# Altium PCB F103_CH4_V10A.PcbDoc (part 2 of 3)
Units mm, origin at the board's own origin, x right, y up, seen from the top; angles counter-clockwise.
Board outline 100.1 x 70.1 mm, 2 copper layers (TOP, BOTTOM), stack 1.6 mm thick; 116 components, 94 nets, 464 pads, 459 vias.
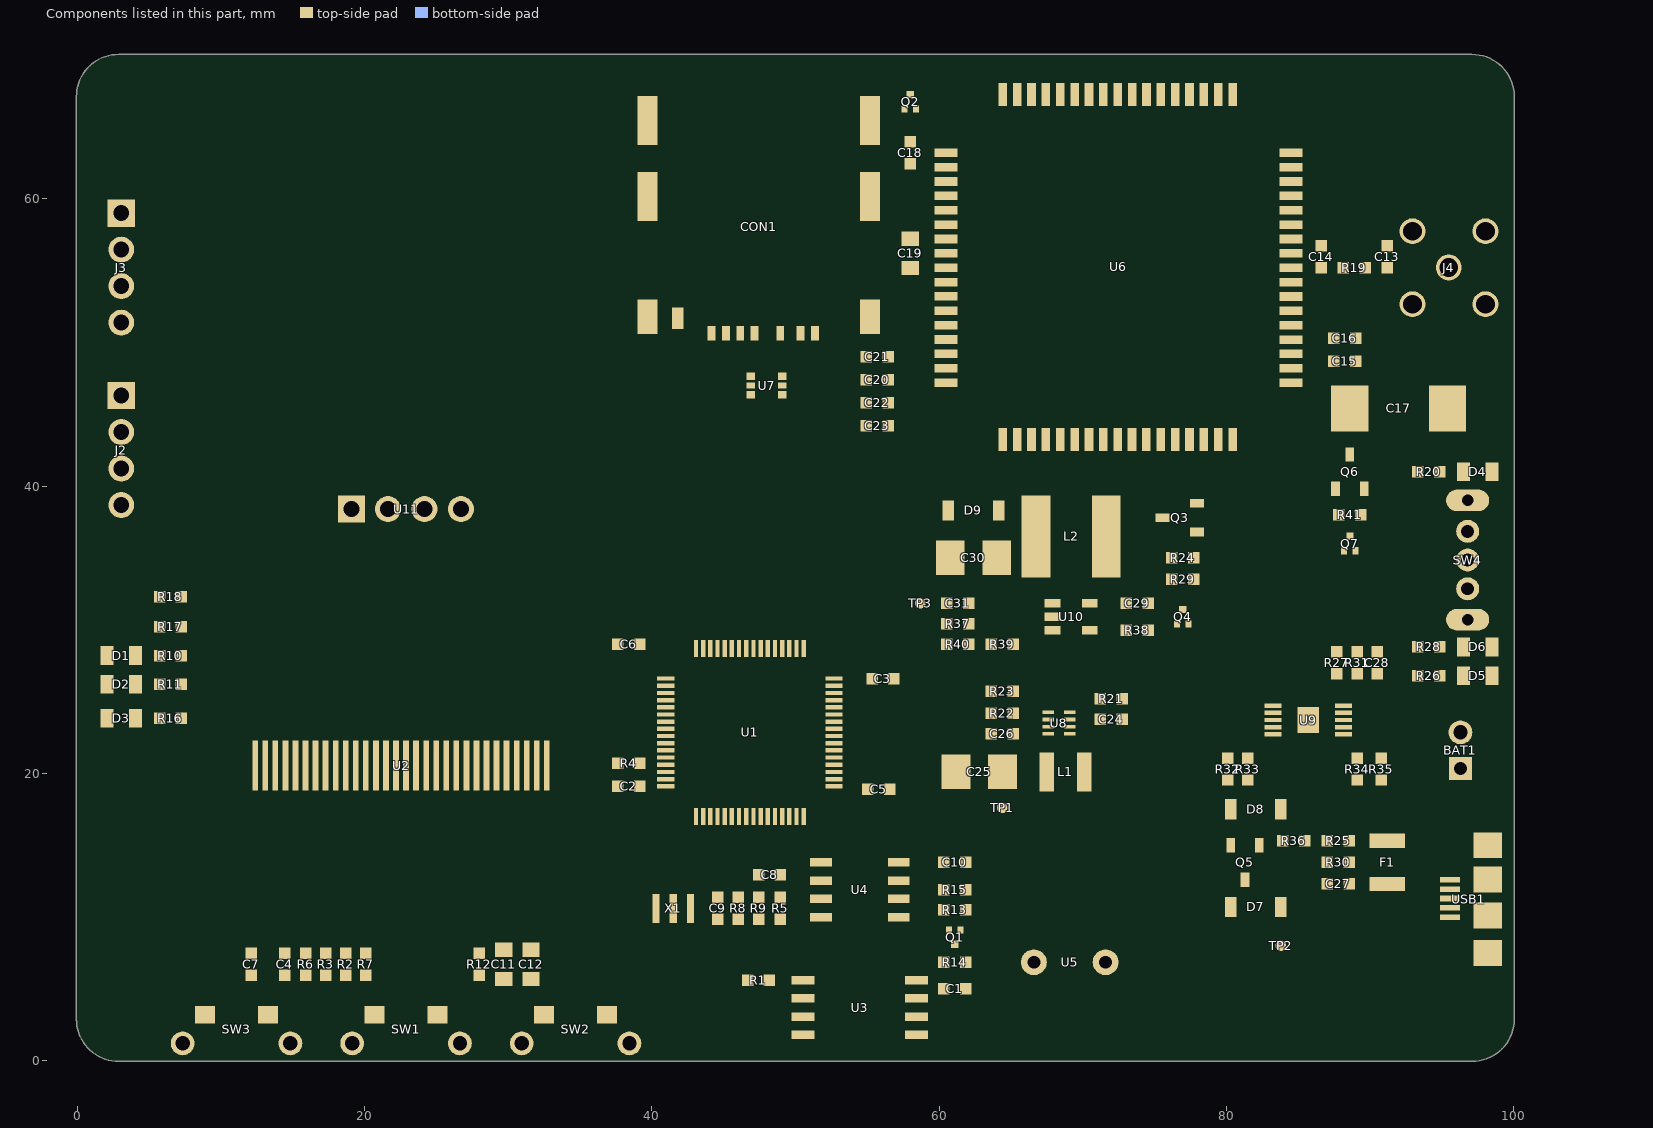
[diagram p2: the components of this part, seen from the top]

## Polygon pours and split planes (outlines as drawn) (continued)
GND on TOP "TOP-GND 38" (solid, pour order 309): 59 vertices, not listed, extent 55.884,43.959 61.941,44.507
GND on TOP "TOP-GND 39" (solid, pour order 310): 67 vertices, not listed, extent 49.791,46.159 53.551,47.091
GND on TOP "TOP-GND 40" (solid, pour order 318): 104 vertices, not listed, extent 55.844,45.559 61.441,47.42
GND on TOP "TOP-GND 41" (solid, pour order 307): 62 vertices, not listed, extent 55.884,47.159 59.168,49.434
GND on TOP "TOP-GND 42" (solid, pour order 345): 452 vertices, not listed, extent 1.159,33.759 6.363,54.617
GND on TOP "TOP-GND 43" (solid, pour order 327): 48 vertices, not listed, extent 59.874,64.521 64.881,68.128
GND on TOP "TOP-GND 44" (solid, pour order 311): 55 vertices, not listed, extent 58.257,65.959 61.563,68.941
GND on TOP "TOP-GND 45" (solid, pour order 348): 372 vertices, not listed, extent 32.001,0.2 47.422,4.541
GND on TOP "TOP-GND 46" (solid, pour order 308): 63 vertices, not listed, extent 87.894,14.596 89.443,15.643
GND on TOP "TOP-GND 47" (solid, pour order 358): 131 vertices, not listed, extent 84.478,0.2 99.8,19.547
GND on TOP "TOP-GND 48" (solid, pour order 330): 248 vertices, not listed, extent 53.859,12.459 59.069,20.041
GND on TOP "TOP-GND 49" (solid, pour order 357): 1012 vertices, not listed, extent 1.559,0.2 22.263,25.074
GND on TOP "TOP-GND 50" (solid, pour order 360): 129 vertices, not listed, extent 0.2,1.941 8.441,28.996
GND on TOP "TOP-GND 51" (solid, pour order 322): 195 vertices, not listed, extent 1.159,28.924 7.47,31.563
GND on TOP "TOP-GND 52" (solid, pour order 362): 838 vertices, not listed, extent 51.993,19.159 89.441,40.441
GND on TOP "TOP-GND 53" (solid, pour order 321): 127 vertices, not listed, extent 91.157,38.157 95.201,40.441
GND on TOP "TOP-GND 54" (solid, pour order 323): 228 vertices, not listed, extent 94.648,19.992 97.941,26.016
GND on TOP "TOP-GND 55" (solid, pour order 325): 199 vertices, not listed, extent 27.163,0.2 31.345,3.741
VCC_3.3V on TOP "TOP-VCC_3.3V" (solid, pour order 337): 26 vertices, not listed, extent 63.3,17.2 68,23.2
VCC_3.3V on TOP "TOP-VCC_3.3V 1" (solid, pour order 59): 25 vertices, not listed, extent 40.268,28.785 40.678,29.215
VCC_3.3V on TOP "TOP-VCC_3.3V 2" (solid, pour order 60): 25 vertices, not listed, extent 39.922,28.785 40.332,29.215
VCC_3.3V on TOP "TOP-VCC_3.3V 3" (solid, pour order 210): 21 vertices, not listed, extent 39.13,28.6 39.962,29.4
VCC_3.3V on TOP "TOP-VCC_3.3V 4" (solid, pour order 153): 23 vertices, not listed, extent 42.701,28.1 43.184,29.127
VCC_3.3V on TOP "TOP-VCC_3.3V 5" (solid, pour order 61): 26 vertices, not listed, extent 42.068,16.785 42.478,17.215
VCC_3.3V on TOP "TOP-VCC_3.3V 6" (solid, pour order 270): 23 vertices, not listed, extent 42.332,16.4 43.114,17.6
VCC_3.3V on TOP "TOP-VCC_3.3V 7" (solid, pour order 75): 40.234,19.081 40.382,18.95 41.014,19.1 40.382,19.25 40.234,19.119 40.232,19.108 40.232,19.097 40.233,19.086 40.234,19.081
VCC_3.3V on TOP "TOP-VCC_3.3V 8" (solid, pour order 243): 39.249,18.316 39.562,18.7 39.162,19.163 38.762,18.7 39.075,18.316 39.096,18.309 39.118,18.304 39.14,18.301 39.162,18.3 39.184,18.301 39.206,18.304 39.228,18.309 39.249,18.315 39.249,18.316
VCC_3.3V on TOP "TOP-VCC_3.3V 9" (solid, pour order 209): 21 vertices, not listed, extent 39.13,18.7 39.962,19.5
VCC_3.3V on TOP "TOP-VCC_3.3V 10" (solid, pour order 77): 53.43,20.119 53.282,20.25 52.65,20.1 53.282,19.95 53.43,20.081 53.432,20.092 53.432,20.103 53.431,20.114 53.43,20.119
VCC_3.3V on TOP "TOP-VCC_3.3V 11" (solid, pour order 240): 55.125,18.116 55.438,18.5 55.038,18.964 54.638,18.5 54.951,18.116 54.972,18.109 54.994,18.104 55.016,18.101 55.038,18.1 55.06,18.101 55.082,18.104 55.104,18.109 55.125,18.115 55.125,18.116
VCC_3.3V on TOP "TOP-VCC_3.3V 12" (solid, pour order 241): 61.775,11.285 61.462,10.9 61.862,10.436 62.262,10.9 61.949,11.285 61.928,11.291 61.906,11.296 61.884,11.299 61.862,11.3 61.84,11.299 61.818,11.296 61.796,11.291 61.775,11.285
VCC_3.3V on TOP "TOP-VCC_3.3V 13" (solid, pour order 246): 62.646,11.987 62.262,12.3 61.798,11.9 62.262,11.5 62.646,11.813 62.653,11.834 62.658,11.856 62.661,11.878 62.662,11.9 62.661,11.922 62.658,11.944 62.653,11.966 62.647,11.987 62.646,11.987
VCC_3.3V on TOP "TOP-VCC_3.3V 14" (solid, pour order 234): 61.949,11.115 62.262,11.5 61.862,11.963 61.462,11.5 61.775,11.115 61.796,11.109 61.818,11.104 61.84,11.101 61.862,11.1 61.884,11.101 61.906,11.104 61.928,11.109 61.949,11.115
VCC_3.3V on TOP "TOP-VCC_3.3V 15" (solid, pour order 78): 53.43,26.619 53.282,26.75 52.65,26.6 53.282,26.45 53.43,26.581 53.432,26.592 53.432,26.603 53.431,26.614 53.43,26.619
VCC_3.3V on TOP "TOP-VCC_3.3V 16" (solid, pour order 217): 21 vertices, not listed, extent 54.538,26.2 55.37,27
VCC_3.3V on TOP "TOP-VCC_3.3V 17" (solid, pour order 268): 27 vertices, not listed, extent 63.238,23.673 64.239,24.6
VCC_3.3V on TOP "TOP-VCC_3.3V 18" (solid, pour order 245): 18.085,6.025 17.7,6.338 17.237,5.938 17.7,5.538 18.085,5.851 18.091,5.872 18.096,5.894 18.099,5.916 18.1,5.938 18.099,5.96 18.096,5.982 18.091,6.004 18.085,6.025
VCC_3.3V on TOP "TOP-VCC_3.3V 19" (solid, pour order 251): 17.915,5.851 18.3,5.538 18.764,5.938 18.3,6.338 17.915,6.025 17.909,6.004 17.904,5.982 17.901,5.96 17.9,5.938 17.901,5.916 17.904,5.894 17.909,5.872 17.915,5.851
VCC_3.3V on TOP "TOP-VCC_3.3V 20" (solid, pour order 301): 19 vertices, not listed, extent 25.037,2.6 26.4,3.8
VCC_3.3V on TOP "TOP-VCC_3.3V 21" (solid, pour order 248): 8.046,23.932 7.662,24.245 7.198,23.845 7.662,23.445 8.046,23.758 8.053,23.779 8.058,23.8 8.061,23.822 8.062,23.844 8.061,23.867 8.058,23.889 8.053,23.91 8.047,23.931 8.046,23.932
VCC_3.3V on TOP "TOP-VCC_3.3V 22" (solid, pour order 247): 8.046,26.287 7.662,26.6 7.198,26.2 7.662,25.8 8.046,26.113 8.053,26.134 8.058,26.156 8.061,26.178 8.062,26.2 8.061,26.222 8.058,26.244 8.053,26.266 8.047,26.287 8.046,26.287
VCC_3.3V on TOP "TOP-VCC_3.3V 23" (solid, pour order 242): 8.046,28.287 7.662,28.6 7.198,28.2 7.662,27.8 8.046,28.113 8.053,28.134 8.058,28.156 8.061,28.178 8.062,28.2 8.061,28.222 8.058,28.244 8.053,28.266 8.047,28.287 8.046,28.287
VCC_3.3V on TOP "TOP-VCC_3.3V 24" (solid, pour order 244): 4.954,32.213 5.338,31.9 5.801,32.3 5.338,32.7 4.954,32.387 4.947,32.366 4.942,32.344 4.939,32.322 4.938,32.3 4.939,32.278 4.942,32.256 4.947,32.234 4.953,32.213 4.954,32.213
VCC_3.3V on TOP "TOP-VCC_3.3V 25" (solid, pour order 235): 59.554,13.713 59.938,13.4 60.401,13.8 59.938,14.2 59.554,13.887 59.547,13.866 59.542,13.844 59.539,13.822 59.538,13.8 59.539,13.778 59.542,13.756 59.547,13.734 59.553,13.713 59.554,13.713
VCC_3.3V on TOP "TOP-VCC_3.3V 26" (solid, pour order 159): 58.232,13.838 57.935,14.1 57.122,13.8 57.935,13.5 58.232,13.762 58.234,13.784 58.235,13.806 58.233,13.828 58.232,13.838
VCC_3.3V on TOP "TOP-VCC_3.3V 27" (solid, pour order 254): 49.407,3.04 49.735,2.765 50.598,3.063 49.735,3.365 49.411,3.174 49.406,3.153 49.402,3.131 49.4,3.109 49.4,3.087 49.403,3.065 49.407,3.043 49.407,3.04
VCC_3.3V on TOP "TOP-VCC_3.3V 28" (solid, pour order 253): 45.882,5.509 46.27,5.205 46.734,5.606 46.27,6.005 45.881,5.689 45.874,5.668 45.869,5.646 45.866,5.624 45.865,5.602 45.866,5.58 45.869,5.558 45.873,5.536 45.88,5.515 45.882,5.509
VCC_3.3V on TOP "TOP-VCC_3.3V 29" (solid, pour order 249): 46.757,4.821 47.07,5.205 46.67,5.669 46.27,5.205 46.583,4.821 46.604,4.814 46.626,4.809 46.648,4.806 46.67,4.805 46.692,4.806 46.714,4.809 46.736,4.814 46.757,4.82 46.757,4.821
VCC_3.3V on TOP "TOP-VCC_3.3V 30" (solid, pour order 233): 49.049,9.053 49.362,9.438 48.962,9.901 48.562,9.438 48.875,9.053 48.896,9.047 48.918,9.042 48.94,9.039 48.962,9.038 48.984,9.039 49.006,9.042 49.028,9.047 49.049,9.053
VCC_3.3V on TOP "TOP-VCC_3.3V 31" (solid, pour order 295): 26 vertices, not listed, extent 65.432,6.214 66.663,7.486
VCC_3.3V on TOP "TOP-VCC_3.3V 32" (solid, pour order 250): 62.646,6.937 62.262,7.25 61.798,6.85 62.262,6.45 62.646,6.763 62.653,6.784 62.658,6.806 62.661,6.828 62.662,6.85 62.661,6.872 62.658,6.894 62.653,6.916 62.647,6.937 62.646,6.937
VCC_3.3V on TOP "TOP-VCC_3.3V 33" (solid, pour order 287): 30 vertices, not listed, extent 61.208,5.87 62.262,7.25
VCC_3.3V on TOP "TOP-VCC_3.3V 34" (solid, pour order 227): 59.532,5.643 59.235,5.905 58.372,5.605 59.235,5.305 59.532,5.567 59.534,5.589 59.535,5.611 59.533,5.633 59.532,5.643
VCC_3.3V on TOP "TOP-VCC_3.3V 35" (solid, pour order 226): 59.532,4.373 59.235,4.635 58.372,4.335 59.235,4.035 59.532,4.297 59.534,4.319 59.535,4.341 59.533,4.363 59.532,4.373
VSSA on TOP "TOP-VSSA" (solid, pour order 212): 21 vertices, not listed, extent 47.038,11.33 47.838,12.162
VSSA on TOP "TOP-VSSA 1" (solid, pour order 73): 48.601,16.252 48.732,16.4 48.582,17.032 48.432,16.4 48.563,16.252 48.574,16.25 48.585,16.25 48.596,16.251 48.601,16.252
VSSA on TOP "TOP-VSSA 2" (solid, pour order 213): 21 vertices, not listed, extent 47.038,12.156 47.838,12.988
VDDA on TOP "TOP-VDDA" (solid, pour order 215): 21 vertices, not listed, extent 48.562,11.33 49.362,12.162
VDDA on TOP "TOP-VDDA 1" (solid, pour order 74): 49.101,16.252 49.232,16.4 49.082,17.032 48.932,16.4 49.063,16.252 49.074,16.25 49.085,16.25 49.096,16.251 49.101,16.252
VDDA on TOP "TOP-VDDA 2" (solid, pour order 211): 21 vertices, not listed, extent 48.562,12.156 49.362,12.988
VDDA on TOP "TOP-VDDA 3" (solid, pour order 257): 26 vertices, not listed, extent 48.562,12.925 49.362,13.876
BOOT0 on TOP "TOP-BOOT0" (solid, pour order 119): 40.237,21.069 40.382,20.95 41.007,21.1 40.382,21.25 40.237,21.131 40.235,21.123 40.233,21.114 40.232,21.105 40.232,21.096 40.233,21.087 40.234,21.079 40.237,21.07 40.237,21.069
BOOT0 on TOP "TOP-BOOT0 1" (solid, pour order 276): 33 vertices, not listed, extent 38.762,20.3 40.299,21.202
SWDIO on TOP "TOP-SWDIO" (solid, pour order 291): 25 vertices, not listed, extent 2.174,40.32 3.092,41.238
SWDIO on TOP "TOP-SWDIO 1" (solid, pour order 260): 26 vertices, not listed, extent 6.76,31.9 7.662,32.84
SWDIO on TOP "TOP-SWDIO 2" (solid, pour order 90): 44.051,29.445 43.932,29.3 44.082,28.675 44.232,29.3 44.113,29.445 44.105,29.447 44.096,29.449 44.087,29.45 44.078,29.45 44.069,29.449 44.061,29.448 44.052,29.445 44.051,29.445
SWCLK on TOP "TOP-SWCLK" (solid, pour order 292): 25 vertices, not listed, extent 2.174,42.86 3.092,43.778
SWCLK on TOP "TOP-SWCLK 1" (solid, pour order 261): 26 vertices, not listed, extent 6.76,29.8 7.662,30.74
SWCLK on TOP "TOP-SWCLK 2" (solid, pour order 115): 40.237,26.569 40.382,26.45 41.007,26.6 40.382,26.75 40.237,26.631 40.235,26.623 40.233,26.614 40.232,26.605 40.232,26.596 40.233,26.587 40.234,26.579 40.237,26.57 40.237,26.569
NRST on TOP "TOP-NRST" (solid, pour order 191): 22 vertices, not listed, extent 44.575,10.962 45.4,11.762
NRST on TOP "TOP-NRST 1" (solid, pour order 230): 24 vertices, not listed, extent 45.632,11.337 46.432,12.212
NRST on TOP "TOP-NRST 2" (solid, pour order 195): 22 vertices, not listed, extent 45.232,10.962 46.057,11.762
NRST on TOP "TOP-NRST 3" (solid, pour order 106): 46.051,17.745 45.932,17.6 46.082,16.975 46.232,17.6 46.113,17.745 46.105,17.747 46.096,17.749 46.087,17.75 46.078,17.75 46.069,17.749 46.061,17.748 46.052,17.745 46.051,17.745
NRST on TOP "TOP-NRST 4" (solid, pour order 91): 46.113,16.255 46.232,16.4 46.082,17.025 45.932,16.4 46.051,16.255 46.059,16.253 46.068,16.251 46.077,16.25 46.086,16.25 46.095,16.251 46.103,16.252 46.112,16.255 46.113,16.255
OSC_IN on TOP "TOP-OSC_IN" (solid, pour order 92): 45.113,16.255 45.232,16.4 45.082,17.025 44.932,16.4 45.051,16.255 45.059,16.253 45.068,16.251 45.077,16.25 45.086,16.25 45.095,16.251 45.103,16.252 45.112,16.255 45.113,16.255
OSC_OUT on TOP "TOP-OSC_OUT" (solid, pour order 93): 45.613,16.255 45.732,16.4 45.582,17.025 45.432,16.4 45.551,16.255 45.559,16.253 45.568,16.251 45.577,16.25 45.586,16.25 45.595,16.251 45.603,16.252 45.612,16.255 45.613,16.255
LED1 on TOP "TOP-LED1" (solid, pour order 278): 26 vertices, not listed, extent 1.624,25.448 2.652,26.85
LED1 on TOP "TOP-LED1 1" (solid, pour order 105): 40.237,24.069 40.382,23.95 41.007,24.1 40.382,24.25 40.237,24.131 40.235,24.123 40.233,24.114 40.232,24.105 40.232,24.096 40.233,24.087 40.234,24.079 40.237,24.07 40.237,24.069
USART1_TX on TOP "TOP-USART1_TX" (solid, pour order 290): 26 vertices, not listed, extent 3.049,53.284 4.305,54.556
USART1_TX on TOP "TOP-USART1_TX 1" (solid, pour order 96): 46.051,29.445 45.932,29.3 46.082,28.675 46.232,29.3 46.113,29.445 46.105,29.447 46.096,29.449 46.087,29.45 46.078,29.45 46.069,29.449 46.061,29.448 46.052,29.445 46.051,29.445
N17026724 on TOP "TOP-N17026724" (solid, pour order 184): 22 vertices, not listed, extent 4.938,23.445 5.763,24.245
N17026724 on TOP "TOP-N17026724 1" (solid, pour order 281): 24 vertices, not listed, extent 4.049,23.195 5.174,24.495
USART1_RX on TOP "TOP-USART1_RX" (solid, pour order 289): 26 vertices, not listed, extent 3.049,50.744 4.305,52.016
USART1_RX on TOP "TOP-USART1_RX 1" (solid, pour order 86): 45.551,29.445 45.432,29.3 45.582,28.675 45.732,29.3 45.613,29.445 45.605,29.447 45.596,29.449 45.587,29.45 45.578,29.45 45.569,29.449 45.561,29.448 45.552,29.445 45.551,29.445
SPI1_MISO on TOP "TOP-SPI1_MISO" (solid, pour order 204): 21 vertices, not listed, extent 50.51,4.035 51.635,4.635
SPI1_MISO on TOP "TOP-SPI1_MISO 1" (solid, pour order 89): 53.427,21.631 53.282,21.75 52.657,21.6 53.282,21.45 53.427,21.569 53.429,21.577 53.431,21.586 53.432,21.595 53.432,21.604 53.431,21.613 53.43,21.621 53.427,21.63 53.427,21.631
SPI1_MOSI on TOP "TOP-SPI1_MOSI" (solid, pour order 201): 21 vertices, not listed, extent 58.41,1.495 59.535,2.095
SPI1_MOSI on TOP "TOP-SPI1_MOSI 1" (solid, pour order 118): 53.427,22.131 53.282,22.25 52.657,22.1 53.282,21.95 53.427,22.069 53.429,22.077 53.431,22.086 53.432,22.095 53.432,22.104 53.431,22.113 53.43,22.121 53.427,22.13 53.427,22.131
SPI1_SCK on TOP "TOP-SPI1_SCK" (solid, pour order 200): 21 vertices, not listed, extent 58.41,2.765 59.535,3.365
SPI1_SCK on TOP "TOP-SPI1_SCK 1" (solid, pour order 117): 53.427,21.131 53.282,21.25 52.657,21.1 53.282,20.95 53.427,21.069 53.429,21.077 53.431,21.086 53.432,21.095 53.432,21.104 53.431,21.113 53.43,21.121 53.427,21.13 53.427,21.131
KEY0 on TOP "TOP-KEY0" (solid, pour order 88): 53.427,23.131 53.282,23.25 52.657,23.1 53.282,22.95 53.427,23.069 53.429,23.077 53.431,23.086 53.432,23.095 53.432,23.104 53.431,23.113 53.43,23.121 53.427,23.13 53.427,23.131
KEY0 on TOP "TOP-KEY0 1" (solid, pour order 288): 23 vertices, not listed, extent 32.475,2.6 33.8,3.8
KEY1 on TOP "TOP-KEY1" (solid, pour order 305): 25 vertices, not listed, extent 8.221,3.175 9.595,4.537
KEY1 on TOP "TOP-KEY1 1" (solid, pour order 124): 40.237,26.069 40.382,25.95 41.007,26.1 40.382,26.25 40.237,26.131 40.235,26.123 40.233,26.114 40.232,26.105 40.232,26.096 40.233,26.087 40.234,26.079 40.237,26.07 40.237,26.069
WK_UP on TOP "TOP-WK_UP" (solid, pour order 306): 26 vertices, not listed, extent 20,2.6 21.502,4.002
WK_UP on TOP "TOP-WK_UP 1" (solid, pour order 122): 49.613,16.255 49.732,16.4 49.582,17.025 49.432,16.4 49.551,16.255 49.559,16.253 49.568,16.251 49.577,16.25 49.586,16.25 49.595,16.251 49.603,16.252 49.612,16.255 49.613,16.255
LED0 on TOP "TOP-LED0" (solid, pour order 300): 27 vertices, not listed, extent 1.323,27.55 2.524,28.952
LED0 on TOP "TOP-LED0 1" (solid, pour order 103): 46.551,29.445 46.432,29.3 46.582,28.675 46.732,29.3 46.613,29.445 46.605,29.447 46.596,29.449 46.587,29.45 46.578,29.45 46.569,29.449 46.561,29.448 46.552,29.445 46.551,29.445
IIC_SDA on TOP "TOP-IIC_SDA" (solid, pour order 156): 21 vertices, not listed, extent 57.16,9.69 58.235,10.29
IIC_SDA on TOP "TOP-IIC_SDA 1" (solid, pour order 102): 41.727,25.131 41.582,25.25 40.957,25.1 41.582,24.95 41.727,25.069 41.729,25.077 41.731,25.086 41.732,25.095 41.732,25.104 41.731,25.113 41.73,25.121 41.727,25.13 41.727,25.131
IIC_SCL on TOP "TOP-IIC_SCL" (solid, pour order 104): 41.727,24.631 41.582,24.75 40.957,24.6 41.582,24.45 41.727,24.569 41.729,24.577 41.731,24.586 41.732,24.595 41.732,24.604 41.731,24.613 41.73,24.621 41.727,24.63 41.727,24.631
IIC_SCL on TOP "TOP-IIC_SCL 1" (solid, pour order 157): 21 vertices, not listed, extent 56.135,10.96 57.21,11.56
IIC_SCL on TOP "TOP-IIC_SCL 2" (solid, pour order 155): 21 vertices, not listed, extent 57.16,10.96 58.235,11.56
N17022771 on TOP "TOP-N17022771" (solid, pour order 186): 22 vertices, not listed, extent 77.324,33.475 78.124,34.3
N17022771 on TOP "TOP-N17022771 1" (solid, pour order 188): 22 vertices, not listed, extent 77.324,34.2 78.124,35.025
N17022771 on TOP "TOP-N17022771 2" (solid, pour order 163): 22 vertices, not listed, extent 77.324,34.975 78.124,35.8
N17022771 on TOP "TOP-N17022771 3" (solid, pour order 272): 29 vertices, not listed, extent 77.462,35.763 78.462,36.825
N17023235 on TOP "TOP-N17023235" (solid, pour order 164): 22 vertices, not listed, extent 75.8,32.7 76.6,33.525
CTL_SENSOR on TOP "TOP-CTL_SENSOR" (solid, pour order 107): 49.113,27.955 49.232,28.1 49.082,28.725 48.932,28.1 49.051,27.955 49.059,27.953 49.068,27.951 49.077,27.95 49.086,27.95 49.095,27.951 49.103,27.952 49.112,27.955 49.113,27.955
CTL_SENSOR on TOP "TOP-CTL_SENSOR 1" (solid, pour order 63): 18 vertices, not listed, extent 76.362,29.95 76.762,30.425
N17061059 on TOP "TOP-N17061059" (solid, pour order 151): 21 vertices, not listed, extent 70.475,29.65 71.35,30.25
N17061059 on TOP "TOP-N17061059 1" (solid, pour order 181): 22 vertices, not listed, extent 72.238,29.55 73.063,30.35
VCC_SENSOR on TOP "TOP-VCC_SENSOR" (solid, pour order 340): 69.9,32.5 70.6,33.2 70.6,39.6 75.8,39.6 76.1,39.3 76.1,37.4 73.8,37.4 73.5,37.1 73.5,31.4 70,31.4 70,31.5 69.9,31.6 69.9,32.5
VCC_SENSOR on TOP "TOP-VCC_SENSOR 1" (solid, pour order 286): 29 vertices, not listed, extent 73.908,29.55 74.962,30.892
OLED_D6 on TOP "TOP-OLED_D6" (solid, pour order 120): 40.237,22.069 40.382,21.95 41.007,22.1 40.382,22.25 40.237,22.131 40.235,22.123 40.233,22.114 40.232,22.105 40.232,22.096 40.233,22.087 40.234,22.079 40.237,22.07 40.237,22.069
F_CS on TOP "TOP-F_CS" (solid, pour order 203): 21 vertices, not listed, extent 50.51,5.305 51.635,5.905
F_CS on TOP "TOP-F_CS 1" (solid, pour order 222): 19 vertices, not listed, extent 49.435,5.305 50.567,5.905
F_CS on TOP "TOP-F_CS 2" (solid, pour order 214): 21 vertices, not listed, extent 48.162,5.205 48.994,6.005
F_CS on TOP "TOP-F_CS 3" (solid, pour order 87): 53.427,20.631 53.282,20.75 52.657,20.6 53.282,20.45 53.427,20.569 53.429,20.577 53.431,20.586 53.432,20.595 53.432,20.604 53.431,20.613 53.43,20.621 53.427,20.63 53.427,20.631
N17056586 on TOP "TOP-N17056586" (solid, pour order 304): 26 vertices, not listed, extent 29.1,7.216 30.5,8.516
OLED_D2 on TOP "TOP-OLED_D2" (solid, pour order 84): 51.937,24.569 52.082,24.45 52.707,24.6 52.082,24.75 51.937,24.631 51.935,24.623 51.933,24.614 51.932,24.605 51.932,24.596 51.933,24.587 51.934,24.579 51.937,24.57 51.937,24.569
OLED_D2 on TOP "TOP-OLED_D2 1" (solid, pour order 54): 25 vertices, not listed, extent 25.675,28.784 26.089,29.215
OLED_D2 on TOP "TOP-OLED_D2 2" (solid, pour order 26): 26 vertices, not listed, extent 25.485,23.811 25.916,24.225
OLED_D5 on TOP "TOP-OLED_D5" (solid, pour order 108): 40.237,22.569 40.382,22.45 41.007,22.6 40.382,22.75 40.237,22.631 40.235,22.623 40.233,22.614 40.232,22.605 40.232,22.596 40.233,22.587 40.234,22.579 40.237,22.57 40.237,22.569
BS2 on TOP "TOP-BS2" (solid, pour order 178): 22 vertices, not listed, extent 18.675,7.062 19.5,7.862
BS2 on TOP "TOP-BS2 1" (solid, pour order 175): 22 vertices, not listed, extent 19.7,7.437 20.5,8.262
BS2 on TOP "TOP-BS2 2" (solid, pour order 193): 22 vertices, not listed, extent 19.3,7.062 20.125,7.862
N17050927 on TOP "TOP-N17050927" (solid, pour order 238): 87.354,55.111 87.738,54.798 88.201,55.198 87.738,55.598 87.354,55.285 87.347,55.264 87.342,55.242 87.339,55.22 87.338,55.198 87.339,55.176 87.342,55.154 87.347,55.132 87.353,55.111 87.354,55.111
N17050927 on TOP "TOP-N17050927 1" (solid, pour order 228): 85.586,55.236 85.289,55.498 84.425,55.198 85.289,54.898 85.586,55.16 85.588,55.182 85.589,55.204 85.587,55.226 85.586,55.236
N17050927 on TOP "TOP-N17050927 2" (solid, pour order 232): 87.384,55.285 87,55.598 86.536,55.198 87,54.798 87.384,55.111 87.391,55.132 87.396,55.154 87.399,55.176 87.4,55.198 87.399,55.22 87.396,55.242 87.391,55.264 87.385,55.285 87.384,55.285
N17050927 on TOP "TOP-N17050927 3" (solid, pour order 236): 85.816,55.111 86.2,54.798 86.663,55.198 86.2,55.598 85.816,55.285 85.809,55.264 85.804,55.242 85.801,55.22 85.8,55.198 85.801,55.176 85.804,55.154 85.809,55.132 85.815,55.111 85.816,55.111
N17056584 on TOP "TOP-N17056584" (solid, pour order 189): 22 vertices, not listed, extent 27.6,7.437 28.4,8.262
NETLED on TOP "TOP-NETLED" (solid, pour order 297): 23 vertices, not listed, extent 83.721,46.161 85.259,47.223
NETLED on TOP "TOP-NETLED 1" (solid, pour order 171): 22 vertices, not listed, extent 92.538,40.6 93.363,41.4
OLED_D1 on TOP "TOP-OLED_D1" (solid, pour order 16): 25 vertices, not listed, extent 24.975,27.885 25.389,28.316
OLED_D1 on TOP "TOP-OLED_D1 1" (solid, pour order 36): 25 vertices, not listed, extent 24.784,23.211 25.215,23.625
OLED_D1 on TOP "TOP-OLED_D1 2" (solid, pour order 85): 51.937,24.069 52.082,23.95 52.707,24.1 52.082,24.25 51.937,24.131 51.935,24.123 51.933,24.114 51.932,24.105 51.932,24.096 51.933,24.087 51.934,24.079 51.937,24.07 51.937,24.069
OLED_D0 on TOP "TOP-OLED_D0" (solid, pour order 121): 51.937,23.569 52.082,23.45 52.707,23.6 52.082,23.75 51.937,23.631 51.935,23.623 51.933,23.614 51.932,23.605 51.932,23.596 51.933,23.587 51.934,23.579 51.937,23.57 51.937,23.569
OLED_D0 on TOP "TOP-OLED_D0 1" (solid, pour order 134): 32 vertices, not listed, extent 24.275,27.056 24.789,27.515
OLED_D0 on TOP "TOP-OLED_D0 2" (solid, pour order 53): 25 vertices, not listed, extent 24.085,23.821 24.516,24.235
VCC_GPRS on TOP "TOP-VCC_GPRS" (solid, pour order 343): 37 vertices, not listed, extent 83.7,41.7 89.9,52.5
OLED_RD on TOP "TOP-OLED_RD" (solid, pour order 12): 25 vertices, not listed, extent 23.575,34.685 23.989,35.115
OLED_RD on TOP "TOP-OLED_RD 1" (solid, pour order 39): 25 vertices, not listed, extent 23.384,23.211 23.815,23.625
OLED_RD on TOP "TOP-OLED_RD 2" (solid, pour order 97): 48.551,29.445 48.432,29.3 48.582,28.675 48.732,29.3 48.613,29.445 48.605,29.447 48.596,29.449 48.587,29.45 48.578,29.45 48.569,29.449 48.561,29.448 48.552,29.445 48.551,29.445
OLED_DC on TOP "TOP-OLED_DC" (solid, pour order 45): 25 vertices, not listed, extent 22.175,33.085 22.589,33.516
OLED_DC on TOP "TOP-OLED_DC 1" (solid, pour order 46): 25 vertices, not listed, extent 21.985,23.211 22.415,23.625
OLED_DC on TOP "TOP-OLED_DC 2" (solid, pour order 101): 47.551,29.445 47.432,29.3 47.582,28.675 47.732,29.3 47.613,29.445 47.605,29.447 47.596,29.449 47.587,29.45 47.578,29.45 47.569,29.449 47.561,29.448 47.552,29.445 47.551,29.445
OLED_CS on TOP "TOP-OLED_CS" (solid, pour order 123): 47.051,29.445 46.932,29.3 47.082,28.675 47.232,29.3 47.113,29.445 47.105,29.447 47.096,29.449 47.087,29.45 47.078,29.45 47.069,29.449 47.061,29.448 47.052,29.445 47.051,29.445
OLED_CS on TOP "TOP-OLED_CS 1" (solid, pour order 37): 25 vertices, not listed, extent 20.775,32.384 21.189,32.815
OLED_CS on TOP "TOP-OLED_CS 2" (solid, pour order 28): 26 vertices, not listed, extent 20.585,23.811 21.016,24.225
OLED_D4 on TOP "TOP-OLED_D4" (solid, pour order 113): 40.237,23.069 40.382,22.95 41.007,23.1 40.382,23.25 40.237,23.131 40.235,23.123 40.233,23.114 40.232,23.105 40.232,23.096 40.233,23.087 40.234,23.079 40.237,23.07 40.237,23.069
N17056590 on TOP "TOP-N17056590" (solid, pour order 302): 27 vertices, not listed, extent 31,7.668 32.2,9.051
OLED_RW on TOP "TOP-OLED_RW" (solid, pour order 29): 26 vertices, not listed, extent 22.875,33.884 23.289,34.315
OLED_RW on TOP "TOP-OLED_RW 1" (solid, pour order 50): 25 vertices, not listed, extent 22.685,23.821 23.116,24.235
OLED_RW on TOP "TOP-OLED_RW 2" (solid, pour order 100): 48.051,29.445 47.932,29.3 48.082,28.675 48.232,29.3 48.113,29.445 48.105,29.447 48.096,29.449 48.087,29.45 48.078,29.45 48.069,29.449 48.061,29.448 48.052,29.445 48.051,29.445
OLED_D7 on TOP "TOP-OLED_D7" (solid, pour order 110): 40.237,21.569 40.382,21.45 41.007,21.6 40.382,21.75 40.237,21.631 40.235,21.623 40.233,21.614 40.232,21.605 40.232,21.596 40.233,21.587 40.234,21.579 40.237,21.57 40.237,21.569
N17056380 on TOP "TOP-N17056380" (solid, pour order 274): 29 vertices, not listed, extent 11.738,7.062 12.738,8.291
N17051220 on TOP "TOP-N17051220" (solid, pour order 205): 21 vertices, not listed, extent 80.14,67.225 80.74,68.351
BS1 on TOP "TOP-BS1" (solid, pour order 180): 22 vertices, not listed, extent 15.875,7.062 16.7,7.862
BS1 on TOP "TOP-BS1 1" (solid, pour order 194): 22 vertices, not listed, extent 16.5,7.062 17.325,7.862
OLED_D3 on TOP "TOP-OLED_D3" (solid, pour order 125): 40.237,23.569 40.382,23.45 41.007,23.6 40.382,23.75 40.237,23.631 40.235,23.623 40.233,23.614 40.232,23.605 40.232,23.596 40.233,23.587 40.234,23.579 40.237,23.57 40.237,23.569
UIM_CLK on TOP "TOP-UIM_CLK" (solid, pour order 275): 27 vertices, not listed, extent 59.532,48.798 61.289,49.5
UIM_CLK on TOP "TOP-UIM_CLK 1" (solid, pour order 263): 26 vertices, not listed, extent 54.538,46.898 55.502,47.8
UIM_CLK on TOP "TOP-UIM_CLK 2" (solid, pour order 138): 20 vertices, not listed, extent 46.875,47.4 47.45,47.9
UIM_CLK on TOP "TOP-UIM_CLK 3" (solid, pour order 143): 21 vertices, not listed, extent 46.6,47.625 47.2,48.2
UIM_CLK on TOP "TOP-UIM_CLK 4" (solid, pour order 258): 27 vertices, not listed, extent 50.978,50.15 51.63,51.322
N17051445 on TOP "TOP-N17051445" (solid, pour order 229): 59.392,55.162 59.689,54.9 60.552,55.2 59.689,55.5 59.392,55.238 59.389,55.216 59.389,55.194 59.39,55.172 59.392,55.162
N17051445 on TOP "TOP-N17051445 1" (solid, pour order 273): 19 vertices, not listed, extent 57.937,54.684 59.116,55.684
UIM_DATA on TOP "TOP-UIM_DATA" (solid, pour order 206): 21 vertices, not listed, extent 59.389,49.9 60.514,50.5
UIM_DATA on TOP "TOP-UIM_DATA 1" (solid, pour order 267): 27 vertices, not listed, extent 54.538,48.36 55.44,49.4
UIM_DATA on TOP "TOP-UIM_DATA 2" (solid, pour order 256): 26 vertices, not listed, extent 49.948,50.048 50.63,51.15
UIM_DATA on TOP "TOP-UIM_DATA 3" (solid, pour order 139): 20 vertices, not listed, extent 49.075,47.4 49.65,47.9
UIM_DATA on TOP "TOP-UIM_DATA 4" (solid, pour order 144): 21 vertices, not listed, extent 48.8,47.625 49.4,48.2
N17050921 on TOP "TOP-N17050921" (solid, pour order 298): 26 vertices, not listed, extent 94.298,54.573 95.548,55.852
N17050921 on TOP "TOP-N17050921 1" (solid, pour order 237): 90.446,55.285 90.062,55.598 89.599,55.198 90.062,54.798 90.446,55.111 90.453,55.132 90.458,55.154 90.461,55.176 90.462,55.198 90.461,55.22 90.458,55.242 90.453,55.264 90.447,55.285 90.446,55.285
N17050921 on TOP "TOP-N17050921 2" (solid, pour order 239): 91.984,55.285 91.6,55.598 91.137,55.198 91.6,54.798 91.984,55.111 91.991,55.132 91.996,55.154 91.999,55.176 92,55.198 91.999,55.22 91.996,55.242 91.991,55.264 91.985,55.285 91.984,55.285
N17050921 on TOP "TOP-N17050921 3" (solid, pour order 231): 90.416,55.111 90.8,54.798 91.264,55.198 90.8,55.598 90.416,55.285 90.409,55.264 90.404,55.242 90.401,55.22 90.4,55.198 90.401,55.176 90.404,55.154 90.409,55.132 90.415,55.111 90.416,55.111
UIM_RST on TOP "TOP-UIM_RST" (solid, pour order 202): 21 vertices, not listed, extent 60.463,47.9 61.589,48.5
UIM_RST on TOP "TOP-UIM_RST 1" (solid, pour order 262): 26 vertices, not listed, extent 54.538,45.26 55.44,46.2
UIM_RST on TOP "TOP-UIM_RST 2" (solid, pour order 68): 18 vertices, not listed, extent 46.875,46.8 47.4,47.2
UIM_RST on TOP "TOP-UIM_RST 3" (solid, pour order 69): 18 vertices, not listed, extent 46.4,46.8 46.925,47.2
UIM_RST on TOP "TOP-UIM_RST 4" (solid, pour order 147): 20 vertices, not listed, extent 46.89,49.875 47.44,50.675
N170520860 on TOP "TOP-N170520860" (solid, pour order 197): 22 vertices, not listed, extent 94.837,40.6 95.666,41.4
N170520860 on TOP "TOP-N170520860 1" (solid, pour order 279): 24 vertices, not listed, extent 95.4,40.354 96.525,41.654
CTL_BEEP on TOP "TOP-CTL_BEEP" (solid, pour order 141): 26 vertices, not listed, extent 61.475,8.85 62.05,9.35
CTL_BEEP on TOP "TOP-CTL_BEEP 1" (solid, pour order 48): 26 vertices, not listed, extent 61.911,8.785 62.325,9.216
CTL_BEEP on TOP "TOP-CTL_BEEP 2" (solid, pour order 27): 26 vertices, not listed, extent 61.911,17.084 62.325,17.515
CTL_BEEP on TOP "TOP-CTL_BEEP 3" (solid, pour order 95): 53.427,25.131 53.282,25.25 52.657,25.1 53.282,24.95 53.427,25.069 53.429,25.077 53.431,25.086 53.432,25.095 53.432,25.104 53.431,25.113 53.43,25.121 53.427,25.13 53.427,25.131
N17064279 on TOP "TOP-N17064279" (solid, pour order 293): 25 vertices, not listed, extent 70.7,6.832 71.618,7.75
N17064279 on TOP "TOP-N17064279 1" (solid, pour order 187): 22 vertices, not listed, extent 59.938,6.825 60.738,7.65
N17064279 on TOP "TOP-N17064279 2" (solid, pour order 137): 20 vertices, not listed, extent 61.075,7.85 61.605,8.35
N17064279 on TOP "TOP-N17064279 3" (solid, pour order 136): 20 vertices, not listed, extent 60.6,7.85 61.125,8.35
GPRS_PWRKEY on TOP "TOP-GPRS_PWRKEY" (solid, pour order 14): 25 vertices, not listed, extent 56.575,66.285 56.989,66.716
GPRS_PWRKEY on TOP "TOP-GPRS_PWRKEY 1" (solid, pour order 152): 33 vertices, not listed, extent 56.901,66.001 57.8,66.602
GPRS_PWRKEY on TOP "TOP-GPRS_PWRKEY 2" (solid, pour order 66): 27 vertices, not listed, extent 50.195,30.461 50.517,30.819
GPRS_PWRKEY on TOP "TOP-GPRS_PWRKEY 3" (solid, pour order 98): 50.051,29.445 49.932,29.3 50.082,28.675 50.232,29.3 50.113,29.445 50.105,29.447 50.096,29.449 50.087,29.45 50.078,29.45 50.069,29.449 50.061,29.448 50.052,29.445 50.051,29.445
GPRS_RESET on TOP "TOP-GPRS_RESET" (solid, pour order 2): 25 vertices, not listed, extent 56.575,63.746 56.989,64.177
GPRS_RESET on TOP "TOP-GPRS_RESET 1" (solid, pour order 196): 22 vertices, not listed, extent 57.2,63.562 58.025,64.362
GPRS_RESET on TOP "TOP-GPRS_RESET 2" (solid, pour order 169): 22 vertices, not listed, extent 57.975,63.562 58.8,64.362
GPRS_RESET on TOP "TOP-GPRS_RESET 3" (solid, pour order 207): 21 vertices, not listed, extent 65.14,66.151 65.74,67.276
GPRS_RESET on TOP "TOP-GPRS_RESET 4" (solid, pour order 25): 26 vertices, not listed, extent 51.511,30.585 51.925,31.016
GPRS_RESET on TOP "TOP-GPRS_RESET 5" (solid, pour order 99): 50.551,29.445 50.432,29.3 50.582,28.675 50.732,29.3 50.613,29.445 50.605,29.447 50.596,29.449 50.587,29.45 50.578,29.45 50.569,29.449 50.561,29.448 50.552,29.445 50.551,29.445
VCC_5V_SENSOR on TOP "TOP-VCC_5V_SENSOR" (solid, pour order 359): 27 vertices, not listed, extent 17.9,31.4 61.8,46.1
VCC_5V_SENSOR on TOP "TOP-VCC_5V_SENSOR 1" (solid, pour order 172): 22 vertices, not listed, extent 60.138,30.375 60.938,31.2
VCC_5V_SENSOR on TOP "TOP-VCC_5V_SENSOR 2" (solid, pour order 182): 22 vertices, not listed, extent 60.138,31.05 60.938,31.875
MQ4_AO on TOP "TOP-MQ4_AO" (solid, pour order 128): 17 vertices, not listed, extent 47.432,16.975 47.732,17.768
MQ4_AO on TOP "TOP-MQ4_AO 1" (solid, pour order 43): 25 vertices, not listed, extent 47.385,18.411 47.816,18.825
MQ4_AO on TOP "TOP-MQ4_AO 2" (solid, pour order 11): 25 vertices, not listed, extent 47.211,36.084 47.625,36.515
MQ4_AO on TOP "TOP-MQ4_AO 3" (solid, pour order 294): 26 vertices, not listed, extent 26.702,37.48 27.62,38.418
USART2_TX on TOP "TOP-USART2_TX" (solid, pour order 21): 25 vertices, not listed, extent 56.575,64.585 56.989,65.016
USART2_TX on TOP "TOP-USART2_TX 1" (solid, pour order 199): 21 vertices, not listed, extent 71.14,67.225 71.74,68.351
USART2_TX on TOP "TOP-USART2_TX 2" (solid, pour order 4): 25 vertices, not listed, extent 52.211,15.485 52.625,15.916
USART2_TX on TOP "TOP-USART2_TX 3" (solid, pour order 158): 26 vertices, not listed, extent 50.432,16.298 50.902,17.6
UIM_VDD on TOP "TOP-UIM_VDD" (solid, pour order 208): 21 vertices, not listed, extent 60.463,50.9 61.589,51.5
UIM_VDD on TOP "TOP-UIM_VDD 1" (solid, pour order 264): 26 vertices, not listed, extent 54.538,43.698 55.502,44.6
UIM_VDD on TOP "TOP-UIM_VDD 2" (solid, pour order 142): 21 vertices, not listed, extent 46.6,45.8 47.2,46.375
UIM_VDD on TOP "TOP-UIM_VDD 3" (solid, pour order 140): 20 vertices, not listed, extent 46.35,46.1 46.925,46.6
UIM_VDD on TOP "TOP-UIM_VDD 4" (solid, pour order 148): 20 vertices, not listed, extent 44.89,49.875 45.44,50.675
N17058271 on TOP "TOP-N17058271" (solid, pour order 332): 92.2,8.9 88.4,8.9 88.1,9.2 88.1,12.6 88.2,12.7 92.4,12.7 92.4,9.1 92.2,8.9
N17058271 on TOP "TOP-N17058271 1" (solid, pour order 185): 22 vertices, not listed, extent 88.162,13 88.962,13.825
N17058271 on TOP "TOP-N17058271 2" (solid, pour order 162): 22 vertices, not listed, extent 88.162,12.275 88.962,13.1
N17058271 on TOP "TOP-N17058271 3" (solid, pour order 320): 42 vertices, not listed, extent 80.5,24.6 84,26.9
N17058347 on TOP "TOP-N17058347" (solid, pour order 160): 22 vertices, not listed, extent 81.1,21.037 81.9,21.862
N17058347 on TOP "TOP-N17058347 1" (solid, pour order 116): 82.505,23.182 82.65,23.063 83.275,23.213 82.65,23.363 82.505,23.244 82.503,23.236 82.501,23.227 82.5,23.218 82.5,23.209 82.501,23.2 82.502,23.192 82.505,23.183 82.505,23.182
VCC_DCDC on TOP "TOP-VCC_DCDC" (solid, pour order 356): 68 vertices, not listed, extent 70.8,9.9 81,39.2
VCC_DCDC on TOP "TOP-VCC_DCDC 1" (solid, pour order 265): 27 vertices, not listed, extent 72.186,24.698 73.162,25.6
VCC_DCDC on TOP "TOP-VCC_DCDC 2" (solid, pour order 252): 70.453,23.663 70.838,23.35 71.302,23.75 70.838,24.15 70.453,23.837 70.447,23.816 70.442,23.794 70.439,23.772 70.438,23.75 70.439,23.728 70.442,23.706 70.447,23.684 70.453,23.663
ADC_USB on TOP "TOP-ADC_USB" (solid, pour order 130): 17 vertices, not listed, extent 46.932,16.232 47.232,17.025
ADC_USB on TOP "TOP-ADC_USB 1" (solid, pour order 34): 26 vertices, not listed, extent 46.885,14.075 47.316,14.489
ADC_USB on TOP "TOP-ADC_USB 2" (solid, pour order 58): 25 vertices, not listed, extent 47.082,1.295 47.405,1.618
ADC_USB on TOP "TOP-ADC_USB 3" (solid, pour order 165): 22 vertices, not listed, extent 86.638,14.5 87.438,15.325
ADC_USB on TOP "TOP-ADC_USB 4" (solid, pour order 259): 26 vertices, not listed, extent 86.498,13.298 87.438,14.2
ADC_USB on TOP "TOP-ADC_USB 5" (solid, pour order 167): 22 vertices, not listed, extent 86.638,13.775 87.438,14.6
N17058224 on TOP "TOP-N17058224" (solid, pour order 220): 21 vertices, not listed, extent 94.83,28.4 95.662,29.2
N17058224 on TOP "TOP-N17058224 1" (solid, pour order 284): 23 vertices, not listed, extent 95.4,28.15 96.532,29.45
VCC_USB on TOP "TOP-VCC_USB" (solid, pour order 346): 173 vertices, not listed, extent 81.9,8.9 96.4,18.2
VCC_USB on TOP "TOP-VCC_USB 1" (solid, pour order 146): 94.678,9.947 94.87,9.79 95.602,9.99 94.87,10.19 94.678,10.034 94.674,10.023 94.672,10.012 94.671,10.001 94.67,9.99 94.671,9.979 94.672,9.968 94.674,9.957 94.678,9.947
N17058351 on TOP "TOP-N17058351" (solid, pour order 161): 22 vertices, not listed, extent 88.7,21.037 89.5,21.862
N17058351 on TOP "TOP-N17058351 1" (solid, pour order 112): 88.895,23.244 88.75,23.363 88.125,23.213 88.75,23.063 88.895,23.182 88.897,23.191 88.899,23.199 88.9,23.208 88.9,23.217 88.899,23.226 88.898,23.235 88.895,23.243 88.895,23.244
N17058317 on TOP "TOP-N17058317" (solid, pour order 166): 22 vertices, not listed, extent 79.7,21.037 80.5,21.862
N17058317 on TOP "TOP-N17058317 1" (solid, pour order 127): 82.505,24.182 82.65,24.063 83.275,24.213 82.65,24.363 82.505,24.244 82.503,24.236 82.501,24.227 82.5,24.218 82.5,24.209 82.501,24.2 82.502,24.192 82.505,24.183 82.505,24.182
N17058162 on TOP "TOP-N17058162" (solid, pour order 218): 21 vertices, not listed, extent 94.83,26.4 95.662,27.2
N17058162 on TOP "TOP-N17058162 1" (solid, pour order 283): 23 vertices, not listed, extent 95.4,26.15 96.532,27.45
ADC_BAT on TOP "TOP-ADC_BAT" (solid, pour order 179): 22 vertices, not listed, extent 88.3,28.062 89.125,28.862
ADC_BAT on TOP "TOP-ADC_BAT 1" (solid, pour order 177): 22 vertices, not listed, extent 86.9,28.062 87.725,28.862
ADC_BAT on TOP "TOP-ADC_BAT 2" (solid, pour order 192): 22 vertices, not listed, extent 87.675,28.062 88.5,28.862
ADC_BAT on TOP "TOP-ADC_BAT 3" (solid, pour order 10): 25 vertices, not listed, extent 46.575,40.785 46.989,41.216
ADC_BAT on TOP "TOP-ADC_BAT 4" (solid, pour order 18): 25 vertices, not listed, extent 46.367,18.393 46.798,18.807
ADC_BAT on TOP "TOP-ADC_BAT 5" (solid, pour order 109): 46.551,17.745 46.432,17.6 46.582,16.975 46.732,17.6 46.613,17.745 46.605,17.747 46.596,17.749 46.587,17.75 46.578,17.75 46.569,17.749 46.561,17.748 46.552,17.745 46.551,17.745
N17058321 on TOP "TOP-N17058321" (solid, pour order 173): 22 vertices, not listed, extent 90.4,21.037 91.2,21.862
N17058321 on TOP "TOP-N17058321 1" (solid, pour order 126): 88.895,24.244 88.75,24.363 88.125,24.213 88.75,24.063 88.895,24.182 88.897,24.191 88.899,24.199 88.9,24.208 88.9,24.217 88.899,24.226 88.898,24.235 88.895,24.243 88.895,24.244
N17026648 on TOP "TOP-N17026648" (solid, pour order 282): 24 vertices, not listed, extent 4.049,25.55 5.174,26.85
N17026648 on TOP "TOP-N17026648 1" (solid, pour order 183): 22 vertices, not listed, extent 4.938,25.8 5.763,26.6
N17026623 on TOP "TOP-N17026623" (solid, pour order 280): 24 vertices, not listed, extent 4.049,27.55 5.174,28.85
N17026623 on TOP "TOP-N17026623 1" (solid, pour order 170): 22 vertices, not listed, extent 4.938,27.8 5.763,28.6
USART2_RX on TOP "TOP-USART2_RX" (solid, pour order 33): 26 vertices, not listed, extent 53.285,17.875 53.716,18.289
USART2_RX on TOP "TOP-USART2_RX 1" (solid, pour order 154): 26 vertices, not listed, extent 52.082,18.816 53.384,19.25
USART2_RX on TOP "TOP-USART2_RX 2" (solid, pour order 57): 25 vertices, not listed, extent 56.582,65.395 56.905,65.718
USART2_RX on TOP "TOP-USART2_RX 3" (solid, pour order 198): 21 vertices, not listed, extent 72.14,67.225 72.74,68.351
N17058835 on TOP "TOP-N17058835" (solid, pour order 216): 21 vertices, not listed, extent 70.438,24.8 71.27,25.6
N17058845 on TOP "TOP-N17058845" (solid, pour order 219): 21 vertices, not listed, extent 64.762,24.9 65.562,25.732
N17058845 on TOP "TOP-N17058845 1" (solid, pour order 221): 21 vertices, not listed, extent 64.762,24.168 65.562,25
N17058219 on TOP "TOP-N17058219" (solid, pour order 269): 23 vertices, not listed, extent 82.65,21.963 83.85,22.738
N17058157 on TOP "TOP-N17058157" (solid, pour order 271): 23 vertices, not listed, extent 98.05,25.7 98.95,26.825
N17058157 on TOP "TOP-N17058157 1" (solid, pour order 111): 88.895,23.744 88.75,23.863 88.125,23.713 88.75,23.563 88.895,23.682 88.897,23.691 88.899,23.699 88.9,23.708 88.9,23.717 88.899,23.726 88.898,23.735 88.895,23.743 88.895,23.744
N17060290 on TOP "TOP-N17060290" (solid, pour order 338): 25 vertices, not listed, extent 63.4,31.5 68.5,39.6
N17028213 on TOP "TOP-N17028213" (solid, pour order 135): 20 vertices, not listed, extent 88.35,36.475 88.85,37
N17028213 on TOP "TOP-N17028213 1" (solid, pour order 149): 21 vertices, not listed, extent 87.3,39 87.9,39.825
N17028213 on TOP "TOP-N17028213 2" (solid, pour order 266): 30 vertices, not listed, extent 87.438,37.975 88.238,39.038
N17060340 on TOP "TOP-N17060340" (solid, pour order 150): 21 vertices, not listed, extent 67.05,29.65 67.925,30.25
VCC_BAT on TOP "TOP-VCC_BAT" (solid, pour order 334): 30 vertices, not listed, extent 88.9,36 97.6,40.4
VCC_BAT on TOP "TOP-VCC_BAT 1" (solid, pour order 333): 81,13.1 81.1,13.2 84.3,13.2 84.7,12.8 84.7,7.6 84.3,7.2 82.8,7.2 82.2,7.8 82.2,10.8 81,12 81,13.1
CTL_GPRS on TOP "TOP-CTL_GPRS" (solid, pour order 129): 17 vertices, not listed, extent 49.432,28.675 49.732,29.468
CTL_GPRS on TOP "TOP-CTL_GPRS 1" (solid, pour order 20): 25 vertices, not listed, extent 49.385,30.411 49.816,30.825
CTL_GPRS on TOP "TOP-CTL_GPRS 2" (solid, pour order 133): 50.159,41.572 49.816,41.915 49.576,41.71 49.8,41.5 50.087,41.5 50.159,41.572
CTL_GPRS on TOP "TOP-CTL_GPRS 3" (solid, pour order 132): 20 vertices, not listed, extent 87.75,35.25 88.225,35.75
N17060374 on TOP "TOP-N17060374" (solid, pour order 190): 22 vertices, not listed, extent 61.662,29.6 62.462,30.425
N17060374 on TOP "TOP-N17060374 1" (solid, pour order 176): 22 vertices, not listed, extent 62.838,28.6 63.663,29.4
N17060374 on TOP "TOP-N17060374 2" (solid, pour order 174): 22 vertices, not listed, extent 61.662,28.975 62.462,29.8
N17060374 on TOP "TOP-N17060374 3" (solid, pour order 168): 22 vertices, not listed, extent 62.037,28.6 62.862,29.4
N17058164 on TOP "TOP-N17058164" (solid, pour order 352): 98 vertices, not listed, extent 87.5,19.3 97.6,35.543
N17058164 on TOP "TOP-N17058164 1" (solid, pour order 71): 88.898,24.732 88.75,24.863 88.118,24.713 88.75,24.563 88.898,24.694 88.9,24.705 88.9,24.716 88.899,24.727 88.898,24.732
GND on BOTTOM "BOTTOM-GND" (solid, pour order 364): -0.05,2.9 ccw(c2.9,2.9) 2.9,-0.05 97.1,-0.05 ccw(c97.1,2.9) 100.05,2.899 100.05,2.9 100.05,67.1 100.05,67.101 ccw(c97.1,67.1) 97.1,70.05 2.9,70.05 ccw(c2.9,67.1) -0.05,67.1
GND on BOTTOM "BOTTOM-GND 1" (solid, pour order 328): 152 vertices, not listed, extent 19.961,0.2 25.839,2.489
GND on BOTTOM "BOTTOM-GND 2" (solid, pour order 316): 152 vertices, not listed, extent 27.461,0.2 30.139,2.489
GND on BOTTOM "BOTTOM-GND 3" (solid, pour order 331): 99 vertices, not listed, extent 51.059,31.205 55.985,65.941
VCC_3.3V on BOTTOM "BOTTOM-VCC_3.3V" (solid, pour order 353): 90 vertices, not listed, extent 38.3,13.4 68,19.5
VCC_3.3V on BOTTOM "BOTTOM-VCC_3.3V 1" (solid, pour order 255): 39.291,5.78 38.631,6.439 38.476,5.6 39.111,5.6 39.291,5.78
VCC_3.3V on BOTTOM "BOTTOM-VCC_3.3V 2" (solid, pour order 0): 41.811,16.858 41.885,16.785 42.16,16.979 42.062,17.038 41.99,17.038 41.811,16.858
VCC_3.3V on BOTTOM "BOTTOM-VCC_3.3V 3" (solid, pour order 1): 8.3,23.972 8.3,23.9 8.381,23.786 8.571,24.06 8.48,24.151 8.3,23.972
VCC_3.3V on BOTTOM "BOTTOM-VCC_3.3V 4" (solid, pour order 299): 26 vertices, not listed, extent 2.438,37.486 3.72,38.743
VCC_3.3V on BOTTOM "BOTTOM-VCC_3.3V 5" (solid, pour order 296): 25 vertices, not listed, extent 2.174,38.635 3.119,39.58
VCC_3.3V on BOTTOM "BOTTOM-VCC_3.3V 6" (solid, pour order 303): 28 vertices, not listed, extent 2.06,55.56 3.122,56.504
OLED_D2 on BOTTOM "BOTTOM-OLED_D2" (solid, pour order 15): 26 vertices, not listed, extent 25.485,28.611 25.916,29.025
OLED_D2 on BOTTOM "BOTTOM-OLED_D2 1" (solid, pour order 23): 26 vertices, not listed, extent 25.485,24.175 25.916,24.589
OLED_D1 on BOTTOM "BOTTOM-OLED_D1" (solid, pour order 3): 25 vertices, not listed, extent 24.784,27.711 25.215,28.125
OLED_D1 on BOTTOM "BOTTOM-OLED_D1 1" (solid, pour order 8): 25 vertices, not listed, extent 24.784,23.575 25.215,23.989
OLED_D0 on BOTTOM "BOTTOM-OLED_D0" (solid, pour order 19): 25 vertices, not listed, extent 24.085,26.911 24.516,27.325
OLED_D0 on BOTTOM "BOTTOM-OLED_D0 1" (solid, pour order 22): 25 vertices, not listed, extent 24.085,24.184 24.516,24.599
OLED_RD on BOTTOM "BOTTOM-OLED_RD" (solid, pour order 6): 25 vertices, not listed, extent 23.384,34.511 23.815,34.925
OLED_RD on BOTTOM "BOTTOM-OLED_RD 1" (solid, pour order 9): 25 vertices, not listed, extent 23.384,23.575 23.815,23.989
OLED_DC on BOTTOM "BOTTOM-OLED_DC" (solid, pour order 13): 25 vertices, not listed, extent 21.985,32.911 22.415,33.325
OLED_DC on BOTTOM "BOTTOM-OLED_DC 1" (solid, pour order 5): 25 vertices, not listed, extent 21.985,23.575 22.415,23.989
OLED_CS on BOTTOM "BOTTOM-OLED_CS" (solid, pour order 42): 25 vertices, not listed, extent 20.585,32.211 21.016,32.625
OLED_CS on BOTTOM "BOTTOM-OLED_CS 1" (solid, pour order 24): 26 vertices, not listed, extent 20.585,24.175 21.016,24.589
OLED_RW on BOTTOM "BOTTOM-OLED_RW" (solid, pour order 31): 26 vertices, not listed, extent 22.685,33.711 23.116,34.125
OLED_RW on BOTTOM "BOTTOM-OLED_RW 1" (solid, pour order 17): 25 vertices, not listed, extent 22.685,24.184 23.116,24.599
CTL_BEEP on BOTTOM "BOTTOM-CTL_BEEP" (solid, pour order 32): 26 vertices, not listed, extent 62.085,8.975 62.516,9.389
CTL_BEEP on BOTTOM "BOTTOM-CTL_BEEP 1" (solid, pour order 51): 25 vertices, not listed, extent 62.085,16.911 62.516,17.325
GPRS_PWRKEY on BOTTOM "BOTTOM-GPRS_PWRKEY" (solid, pour order 38): 25 vertices, not listed, extent 56.211,66.285 56.625,66.716
GPRS_PWRKEY on BOTTOM "BOTTOM-GPRS_PWRKEY 1" (solid, pour order 44): 25 vertices, not listed, extent 50.284,30.775 50.715,31.189
GPRS_RESET on BOTTOM "BOTTOM-GPRS_RESET" (solid, pour order 67): 28 vertices, not listed, extent 56.173,63.746 56.625,64.193
GPRS_RESET on BOTTOM "BOTTOM-GPRS_RESET 1" (solid, pour order 52): 25 vertices, not listed, extent 51.684,30.775 52.115,31.189
MQ4_AO on BOTTOM "BOTTOM-MQ4_AO" (solid, pour order 7): 25 vertices, not listed, extent 47.385,18.775 47.816,19.189
MQ4_AO on BOTTOM "BOTTOM-MQ4_AO 1" (solid, pour order 41): 25 vertices, not listed, extent 47.385,35.911 47.816,36.325
USART2_TX on BOTTOM "BOTTOM-USART2_TX" (solid, pour order 131): 31 vertices, not listed, extent 56.579,64.495 57.001,64.843
USART2_TX on BOTTOM "BOTTOM-USART2_TX 1" (solid, pour order 40): 25 vertices, not listed, extent 52.385,15.675 52.816,16.089
N17058271 on BOTTOM "BOTTOM-N17058271" (solid, pour order 350): 18 vertices, not listed, extent 78.4,9.1 92.6,26.9
ADC_USB on BOTTOM "BOTTOM-ADC_USB" (solid, pour order 47): 26 vertices, not listed, extent 46.885,13.711 47.316,14.125
ADC_USB on BOTTOM "BOTTOM-ADC_USB 1" (solid, pour order 56): 25 vertices, not listed, extent 46.885,1.575 47.316,1.989
ADC_BAT on BOTTOM "BOTTOM-ADC_BAT" (solid, pour order 64): 27 vertices, not listed, extent 46.376,40.593 46.815,41.025
ADC_BAT on BOTTOM "BOTTOM-ADC_BAT 1" (solid, pour order 49): 25 vertices, not listed, extent 46.367,18.757 46.798,19.171
USART2_RX on BOTTOM "BOTTOM-USART2_RX" (solid, pour order 35): 26 vertices, not listed, extent 53.285,17.875 53.716,18.289
USART2_RX on BOTTOM "BOTTOM-USART2_RX 1" (solid, pour order 65): 27 vertices, not listed, extent 56.581,65.395 56.939,65.717
VCC_BAT on BOTTOM "BOTTOM-VCC_BAT" (solid, pour order 354): 93 vertices, not listed, extent 81.7,11.7 97.7,37.8
CTL_GPRS on BOTTOM "BOTTOM-CTL_GPRS" (solid, pour order 55): 25 vertices, not listed, extent 49.385,30.775 49.816,31.189
CTL_GPRS on BOTTOM "BOTTOM-CTL_GPRS 1" (solid, pour order 30): 26 vertices, not listed, extent 49.385,41.311 49.816,41.725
